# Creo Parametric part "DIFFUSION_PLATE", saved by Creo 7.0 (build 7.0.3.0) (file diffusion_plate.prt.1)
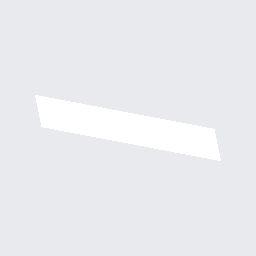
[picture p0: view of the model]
Units: millimeter Kilogram Sec (mmKs); MM, KILOGRAM, SECS

Created from: XX_SOLID_PART_MMKS_ABS.PRT

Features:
  1. coordinate system
  2. datum plane "RIGHT"
  3. datum plane "TOP"
  4. datum plane "FRONT"
  5. extrusion "Extrude 1"

Surfaces: 6 plane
